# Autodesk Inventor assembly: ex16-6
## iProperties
Shininess: 64.0
Length Units: 11269
Angle Units: 11279
Time Units: 11290
Mass Units: 11283
Length Display Precision: 3
Angle Display Precision: 2
Compacted: True
Created: 2002-11
Part Number: ex16-6
Document SubType Name: Assembly
Designer: E. MOSS
Density: 0.0
Volumn: 0.0
Area: 0.0
PropertySet Name: Model Information
Control State: 0
Master: False
Checked Out: False
Author: E. MOSS
